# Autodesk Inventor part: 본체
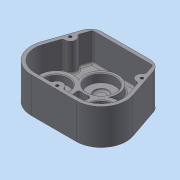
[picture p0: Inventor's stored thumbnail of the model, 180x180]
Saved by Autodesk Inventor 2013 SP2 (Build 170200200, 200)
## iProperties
Created: 2014-12
Part Number: 본체
Material: 일반
Document SubType Name: Modeling
Designer: dgall
Density: 1 g/cm^3
Author: dgall
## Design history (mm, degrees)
sketch "스케치1"
  geometry: L1 (-47, 36)-(47, 36); L2 (0, 36)-(0, -137); L3 (-32.257, -68.257)-(32.257, -68.257); L4 (0, 0)-(-32.257, -32.257); L5 (0, 0)-(32.257, -32.257); L6 (-47, 36)-(-66.327, -20.629); L7 (47, 36)-(66.327, -20.629); A1 r 36 centre (-32.257, -32.257) between (-66.327, -20.629) and (-32.257, -68.257); A2 r 36 centre (32.257, -32.257) between (32.257, -68.257) and (66.327, -20.629)
  constraints: 14 end point, 4 point on circle, 3 tangent, 2 centre point, 1 equal radius, 1 horizontal, 1 horizontal alignment, 1 midpoint, 1 perpendicular, 1 vertical alignment
  dimensions: "d3" = 36 distance from line of L4.start L1; "d4" = 94 distance of L1.start L1.end; "d5" = 36 radius of A1; "d6" = 36 distance from line of L4.end L3; "d7" = 45 deg angle of L4 L2; "d8" = 90 deg angle of L5 L4; "d9" = 32.257 horizontal distance of L5.end L4.start
extrude "돌출1" new body sketch "스케치1" distance "d10" = 51; taper "d11" = 0 deg
sketch "스케치2"
  geometry: L1 (-47, 36)-(47, 36) reference; L2 (-66.327, -20.629)-(-47, 36) reference; L3 (32.257, -68.257)-(-32.257, -68.257) reference; L4 (47, 36)-(66.327, -20.629) reference; L5 (43.423, 31)-(-43.423, 31); L6 (-43.423, 31)-(-61.595, -22.244); L7 (-32.257, -63.257)-(32.257, -63.257); L8 (61.595, -22.244)-(43.423, 31); A1 r 36 centre (-32.257, -32.257) between (-66.327, -20.629) and (-32.257, -68.257) reference; A2 r 36 centre (32.257, -32.257) between (32.257, -68.257) and (66.327, -20.629) reference; A3 r 31 centre (-32.257, -32.257) between (-61.595, -22.244) and (-32.257, -63.257); A4 r 31 centre (32.257, -32.257) between (32.257, -63.257) and (61.595, -22.244); 1 further point
  constraints: 8 end point, 4 point on circle, 2 centre point, 5 other
  dimensions: "d12" = 5 distance between parallel lines of L5 L1
extrude "돌출2" cut sketch "스케치2" distance "d13" = 41; taper "d14" = 0 deg
sketch "스케치11"
  geometry: C1 r 20 at (-32.257, -32.257); C2 r 20 at (32.257, -32.257); A1 r 36 centre (-32.257, -32.257) between (-66.327, -20.629) and (-32.257, -68.257) reference; A2 r 36 centre (32.257, -32.257) between (32.257, -68.257) and (66.327, -20.629) reference; 1 further point
  constraints: 2 centre point, 2 coincident, 1 equal radius
  dimensions: "d44" = 40 diameter of C1
extrude "돌출10" join sketch "스케치11" distance "d46" = 7; taper "d47" = -10 deg
sketch "스케치12"
  geometry: C1 r 18.766 at (0, 0) reference; C2 r 18.766 at (64.514, 0) reference; C3 r 15 at (0, 0); C4 r 15 at (64.514, 0); 1 further point
  constraints: 2 centre point, 2 coincident, 1 equal radius
  dimensions: "d48" = 30 diameter of C3
extrude "돌출11" cut sketch "스케치12" distance "d50" = 7; taper "d51" = 0 deg
sketch "스케치14"
  geometry: C1 r 24 at (0, 0); 1 further point
  constraints: 2 coincident, 1 centre point
  dimensions: "d56" = 48 diameter of C1
extrude "돌출12" join sketch "스케치14" distance "d58" = 11; taper "d59" = 0 deg
sketch "스케치15"
  geometry: C1 r 24 at (0, 0) reference; C2 r 20 at (0, 0)
  constraints: 1 centre point, 1 coincident
  dimensions: "d60" = 40 diameter of C2
extrude "돌출13" cut sketch "스케치15" distance "d62" = 12; taper "d63" = 0 deg
sketch "스케치16"
  geometry: C1 r 20 at (0, 0) reference; C2 r 10 at (0, 0)
  constraints: 1 centre point, 1 coincident
  dimensions: "d64" = 20 diameter of C2
extrude "돌출14" cut sketch "스케치16" distance "d66" = 3; taper "d67" = 0 deg
sketch "스케치17"
  geometry: C1 r 24 at (0, 0) reference; C2 r 24 at (-32.257, -32.257); C3 r 24 at (32.257, -32.257); A1 r 31 centre (-32.257, -32.257) between (-61.595, -22.244) and (-32.257, -63.257) reference; A2 r 31 centre (32.257, -32.257) between (32.257, -63.257) and (61.595, -22.244) reference
  constraints: 2 centre point, 2 coincident, 2 equal radius
extrude "돌출15" join sketch "스케치17" distance "d68" = 11; taper "d69" = 0 deg
sketch "스케치18"
  geometry: C1 r 24 at (0, 0) reference; C2 r 24 at (45.618, 45.618) reference; C3 r 17.5 at (0, 0); C4 r 17.5 at (45.618, 45.618); 1 further point
  constraints: 2 centre point, 2 coincident, 1 equal radius
  dimensions: "d70" = 35 diameter of C3
extrude "돌출16" cut sketch "스케치18" distance "d72" = 11; taper "d73" = 0 deg
sketch "스케치19"
  geometry: C1 r 17.5 at (0, 0) reference; C2 r 17.5 at (64.514, 0) reference; C3 r 7.75 at (0, 0); C4 r 7.75 at (64.514, 0); 1 further point
  constraints: 2 centre point, 2 coincident, 1 equal radius
  dimensions: "d74" = 15.5 diameter of C3
extrude "돌출17" cut sketch "스케치19" distance "d76" = 10; taper "d77" = 0 deg
sketch "스케치20"
  geometry: L1 (-61.595, -22.244)-(-43.423, 31) reference; L2 (43.423, 31)-(61.595, -22.244) reference; L3 (-47, 36)-(47, 36) reference; A1 r 8 centre (-51.614, 7) between (-54.198, -0.571) and (-49.03, 14.571); A2 r 8 centre (51.614, 7) between (49.03, 14.571) and (54.198, -0.571); 1 further point
  constraints: 6 point on line, 4 point on circle, 2 centre point, 1 equal radius, 1 horizontal alignment
  dimensions: "d78" = 29 distance from line of L3 A1.centre; "d79" = 8 radius of A1
extrude "돌출18" join sketch "스케치20" stored distance "d80" = 10; taper "d81" = 0 deg
sketch "스케치21"
  geometry: L1 (32.257, -63.257)-(-32.257, -63.257) reference; A1 r 8 centre (0, -63.257) between (8, -63.257) and (-8, -63.257); 2 further points
  constraints: 2 midpoint, 2 point on circle, 2 point on line, 1 centre point, 1 vertical alignment
  dimensions: "d82" = 8 radius of A1
extrude "돌출19" join sketch "스케치21" stored distance "d84" = 10; taper "d85" = 0 deg
sketch "스케치22"
  geometry: A1 r 8 centre (0, -63.257) between (8, -63.257) and (-8, -63.257) reference; A2 r 8 centre (-51.614, 7) between (-54.198, -0.571) and (-49.03, 14.571) reference; A3 r 8 centre (51.614, 7) between (49.03, 14.571) and (54.198, -0.571) reference; 4 further points
  constraints: 3 coincident
hole "구멍1" sketch "스케치22" at (-51.614, 7), (0, -63.257), (51.614, 7) diameter "d86" = 4.134; stored, may be unused: countersink angle "d90" = 90 deg, drill point angle "d92" = 118 deg; dims "d87" = 20, "d88" = 4, "d89" = 2, "d91" = 23
sketch "스케치23"
  geometry: L1 (47, 36)-(-47, 36) reference; 2 further points
  constraints: 1 vertical alignment, 1 other
  dimensions: "d93" = 30 distance from line of L1 point (0, 6)
feature "엠보싱1" sketch "스케치23" dims "d3" = 36, "d4" = 94, "d5" = 36, "d6" = 36, "d7" = 45 deg, "d8" = 90 deg, "d9" = 32.257, "d94" = 1, "d95" = 0
fillet "모깎기3" dims "d98" = 3
fillet "모깎기4" dims "d99" = 3
fillet "모깎기5" dims "d100" = 3
fillet "모깎기6" dims "d101" = 3
fillet "모깎기7" dims "d102" = 3
chamfer "모따기1" distance "d103" = 1; stored, may be unused: second distance "d104" = 2, angle "d105" = 45 deg
fillet "모깎기8" dims "d106" = 0.1
chamfer "모따기2" distance "d107" = 1; stored, may be unused: second distance "d108" = 2, angle "d109" = 45 deg
fillet "모깎기9" dims "d110" = 0.3
fillet "모깎기10" dims "d111" = 3
fillet "모깎기11" dims "d112" = 18
node "솔리드1"
